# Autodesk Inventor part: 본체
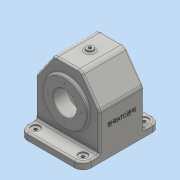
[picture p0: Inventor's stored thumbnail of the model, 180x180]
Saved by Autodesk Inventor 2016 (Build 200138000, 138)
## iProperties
Created: 2022-12
Part Number: 본체
Material: 일반
Document SubType Name: Modeling
Designer: PC-1-2
Density: 1 g/cm^3
Appearance: 기본값
Author: PC-1-2
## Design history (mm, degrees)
sketch "스케치1"
  geometry: L1 (-55, -67)-(55, -67); L2 (55, -67)-(55, 67); L3 (55, 67)-(-55, 67); L4 (-55, 67)-(-55, -67); L5 (-55, -67)-(55, 67); L6 (55, -67)-(-55, 67); 1 further point
  constraints: 12 end point, 2 midpoint, 2 parallel, 1 horizontal, 1 perpendicular
  dimensions: "d0" = 134 distance between parallel lines of L1 L3; "d1" = 110 distance between parallel lines of L2 L4
extrude "돌출1" new body sketch "스케치1" distance "d2" = 12; taper "d3" = 0 deg
sketch "스케치2"
  geometry: L1 (55, 12)-(-55, 12) reference; L2 (55, 12)-(55, 77); L3 (55, 77)-(23.491, 122); L4 (23.491, 122)-(-23.491, 122); L5 (-23.491, 122)-(-55, 77); L6 (-55, 77)-(-55, 12); L7 (55, 0)-(-55, 0) reference; 1 further point
  constraints: 10 end point, 1 horizontal alignment, 1 parallel, 1 perpendicular, 1 vertical
  dimensions: "d4" = 122 distance between parallel lines of L7 L4; "d5" = 77 distance from line of L7 L2.end; "d6" = 35 deg angle of L3 L2; "d7" = 35 deg angle of L6 L5
extrude "돌출2" join sketch "스케치2" stored distance "d8" = 77; taper "d9" = 0 deg
sketch "스케치3"
  geometry: C1 r 6 at (23.491, -38.5); 1 further point
  constraints: 1 centre point, 1 coincident
  dimensions: "d10" = 12 diameter of C1
extrude "돌출3" join sketch "스케치3" distance "d11" = 4; taper "d12" = 0 deg
sketch "스케치4"
  geometry: L1 (-55, 0)-(55, 0) reference; C1 r 37.5 at (0, 65); 2 further points
  constraints: 1 centre point, 1 midpoint, 1 vertical alignment
  dimensions: "d13" = 75 diameter of C1; "d14" = 65 distance from line of L1 C1.centre
extrude "돌출4" join sketch "스케치4" distance "d15" = 5; taper "d16" = 0 deg
sketch "스케치5"
  geometry: L1 (55, 0)-(-55, 0) reference; C1 r 31 at (0, -65); 2 further points
  constraints: 1 centre point, 1 midpoint, 1 vertical alignment
  dimensions: "d17" = 65 distance from line of L1 C1.centre; "d18" = 62 diameter of C1
extrude "돌출5" join sketch "스케치5" distance "d19" = 10; taper "d20" = 0 deg
sketch "스케치6"
  geometry: L1 (55, 77)-(23.491, 122) reference; L2 (23.491, 122)-(-23.491, 122) reference; L3 (-23.491, 122)-(-55, 77) reference; L4 (-55, 77)-(-55, 12) reference; L5 (55, 12)-(55, 77) reference; L6 (55, 0)-(55, 12) reference; L7 (-55, 0)-(-55, 12) reference; L8 (-50, 0)-(-50, 12); L9 (-50, 12)-(-50, 75.424); L10 (-50, 75.424)-(-20.888, 117); L11 (-20.888, 117)-(20.888, 117); L12 (20.888, 117)-(50, 75.424); L13 (50, 75.424)-(50, 12); L14 (50, 12)-(50, 0); L15 (50, 0)-(-50, 0); 2 further points
  constraints: 16 end point, 1 horizontal alignment, 1 midpoint, 1 perpendicular, 6 other
  dimensions: "d21" = 5 distance between parallel lines of L1 L12
extrude "돌출6" cut sketch "스케치6" stored distance "d22" = 67; taper "d23" = 0 deg
sketch "스케치7"
  geometry: C1 r 27 at (0, -65); C2 r 37.5 at (0, -65) reference; 1 further point
  constraints: 1 centre point, 1 concentric
  dimensions: "d24" = 54 diameter of C1
extrude "돌출7" join sketch "스케치7" distance "d25" = 14; taper "d26" = 0 deg
feature "면 기울기1" dims angle "d27" = 45 deg
hole "구멍1" diameter "d30" = 40; stored, may be unused: countersink angle "d34" = 90 deg, drill point angle "d36" = 0 deg; dims "d28" = 10, "d29" = 10, "d31" = 6, "d32" = 4, "d33" = 2, "d35" = 100
sketch "스케치8" dims "d37" = 58
  geometry: C1 r 37.5 at (0, 0) reference; 3 further points
  constraints: 2 vertical alignment, 3 other
hole "구멍2" sketch "스케치8" at (0, 29) diameter "d38" = 2.459; stored, may be unused: countersink angle "d42" = 90 deg, drill point angle "d44" = 118 deg; dims "d39" = 6, "d40" = 4, "d41" = 2, "d43" = 8
sketch "스케치9" dims "d48" = 52
  geometry: C1 r 31 at (0, 0) reference; 3 further points
  constraints: 2 vertical alignment, 3 other
hole "구멍3" sketch "스케치9" at (0, -26) diameter "d49" = 2.459; stored, may be unused: countersink angle "d53" = 90 deg, drill point angle "d55" = 118 deg; dims "d50" = 6, "d51" = 4, "d52" = 2, "d54" = 8
hole "구멍4" diameter "d61" = 5.188; stored, may be unused: countersink angle "d65" = 90 deg, drill point angle "d67" = 0 deg; dims "d59" = 10, "d60" = 10, "d62" = 61, "d63" = 4, "d64" = 2, "d66" = 61
fillet "모깎기1" dims "d68" = 14
hole "구멍5" diameter "d71" = 5.5; stored, may be unused: countersink angle "d75" = 90 deg, drill point angle "d77" = 0 deg; dims "d69" = 10, "d70" = 10, "d72" = 61, "d73" = 15, "d74" = 2, "d76" = 12
fillet "모깎기2" dims "d84" = 10
fillet "모깎기3" dims "d85" = 3
fillet "모깎기4" dims "d86" = 3
fillet "모깎기5" dims "d87" = 3
fillet "모깎기6" dims "d88" = 3
fillet "모깎기7" dims "d89" = 5
fillet "모깎기8" dims "d90" = 3
fillet "모깎기9" dims "d91" = 3
chamfer "모따기1" distance "d92" = 1; stored, may be unused: second distance "d93" = 2, angle "d94" = 45 deg
sketch "스케치10"
  geometry: L1 (-54, 28)-(-54, 78); L2 (-54, 78)-(-46, 78); L3 (-46, 78)-(-46, 28); L4 (-46, 28)-(-54, 28); L5 (-50, 28)-(-50, 78); L6 (-54, 53)-(-46, 53); L7 (0, 0)-(0, 106) reference; L8 (-73.847, 14.5)-(-15, 14.5) reference; 1 further point
  constraints: 4 end point, 4 midpoint, 2 other
  dimensions: "d95" = 8 distance between parallel lines of L3 L1; "d96" = 50 distance between parallel lines of L4 L2; "d97" = 50 distance between parallel lines of L7 L5; "d98" = 38.5 distance between parallel lines of L8 L6
feature "엠보싱1" sketch "스케치10" dims "d0" = 134, "d1" = 110, "d99" = 0.5, "d100" = 0
node "솔리드1"
pattern_circular "원형 패턴1" dims angle "d46" = 360 deg
pattern_circular "원형 패턴2" dims angle "d57" = 360 deg
pattern_linear "직사각형 패턴1" dims "d80" = 82, "d83" = 106
